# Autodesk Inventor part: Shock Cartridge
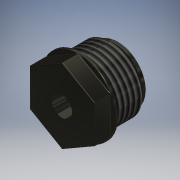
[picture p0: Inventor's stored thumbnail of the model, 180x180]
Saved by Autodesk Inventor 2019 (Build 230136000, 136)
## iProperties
Shininess: 50.0
Compacted: True
Length Units: 11272
Angle Units: 11279
Time Units: 11290
Mass Units: 11286
Length Display Precision: 4
Angle Display Precision: 2
Company: Autodesk
Created: 2000-03
Part Number: Shock Cartridge
Project: Inventor Samples
User Status: IN PROGRESS
Document SubType Name: Modeling
Designer: Autodesk, Inc.
Density: 1.13 g/cm^3
Mass: 0.726089 g
Surface Area: 7.62144 cm^2
Volume: 0.642557 cm^3
Material: Nylon-6/6
Appearance: Gunmetal
Density: 0.0
Volumn: 0.0
Area: 0.0
PropertySet Name: Model Information
Control State: 0
Master: False
Checked Out: False
Checked Out Date: 2018-05-30
Last Check In Date: 2018-05-30
Author: Autodesk, Inc.
Revision Number: A
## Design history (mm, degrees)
node "Extrusion1" dims "d1" = 3.175, "d2" = 0
  sketch "Sketch2"
    geometry: C1 r 6.35 at (9.288, -0.006)
    constraints: 1 centre point
    dimensions: "d0" = 12.7 diameter of C1
node "Extrusion4" dims "d8" = 2.794 (computed from d1), "d9" = 0
  sketch "Sketch3"
    geometry: L1 (-5.499, 3.175)-(-5.499, -3.175); L2 (-5.499, -3.175)-(0, -6.35); L3 (0, -6.35)-(5.499, -3.175); L4 (5.499, -3.175)-(5.499, 3.175); L5 (5.499, 3.175)-(0, 6.35); L6 (0, 6.35)-(-5.499, 3.175); L7 (-5.499, 3.175)-(-6.35, 3.175); L8 (-6.35, 3.175)-(-6.35, -3.175); L9 (-6.35, -3.175)-(-5.499, -3.175); C1 r 6.35 at (0, 0) reference; C2 r 5.499 at (0, 0)
    constraints: 18 end point, 7 tangent, 4 equal length, 2 parallel, 2 perpendicular, 1 centre point, 1 coincident, 1 vertical
    dimensions: "d3" = 12.7 distance of L2.end L5.end (= d0)
node "Circular Pattern1" dims "d10" = 60, "d12" = 60 deg
node "Fillet1" dims "d13" = 0.127
node "Extrusion5" dims "d15" = 6.35, "d16" = 0
  sketch "Sketch5"
    geometry: C1 r 5.461 at (0, 0); C2 r 6.35 at (0, 0) reference
    constraints: 1 centre point, 1 coincident
    dimensions: "d14" = 10.922 diameter of C1
node "Extrusion6" dims "d18" = 7.366, "d19" = 0
  sketch "Sketch6"
    geometry: C1 r 5.461 at (0, 0) reference; C2 r 3.175 at (0, 0)
    constraints: 1 centre point, 1 coincident
    dimensions: "d17" = 6.35 diameter of C2
node "Hole1" dims "d20" = 3.429, "d21" = 9.525, "d22" = 6.35, "d23" = 60 deg, "d24" = 19.05, "d25" = 118 deg
  sketch "Sketch8"
    geometry: C1 r 6.35 at (9.288, -0.006) reference
workaxis "Work Axis1"
workplane "Work Plane1"
node "Revolution1" dims "d31" = 90 deg
  sketch "Sketch9"
    geometry: L1 (5.461, -6.35)-(-5.461, -6.35) reference; L2 (-5.461, 0)-(-5.461, -6.35) reference; L3 (-4.762, -6.35)-(-4.763, -5.715); L4 (-4.763, -5.715)-(-4.127, -5.715); L5 (-4.127, -5.715)-(-4.128, -5.08); L6 (-4.128, -5.08)-(-5.461, -5.08); L7 (0, 5.08)-(0, -8.255) reference
    constraints: 8 end point, 2 parallel, 2 perpendicular, 2 point on line
    dimensions: "d27" = 1.27 distance between parallel lines of L1 L6; "d28" = 0.635 distance between parallel lines of L1 L4 (= 0.5 x d27); "d29" = 0.635 distance between parallel lines of L5 L3; "d30" = 9.525 diameter of L3 L7
node "Fillet2" dims "d32" = 0.127
thread "Thread1" dims "d33" = 25.4, "d34" = 0
body "Solid1"
other parameters: "d26" = 90 deg
